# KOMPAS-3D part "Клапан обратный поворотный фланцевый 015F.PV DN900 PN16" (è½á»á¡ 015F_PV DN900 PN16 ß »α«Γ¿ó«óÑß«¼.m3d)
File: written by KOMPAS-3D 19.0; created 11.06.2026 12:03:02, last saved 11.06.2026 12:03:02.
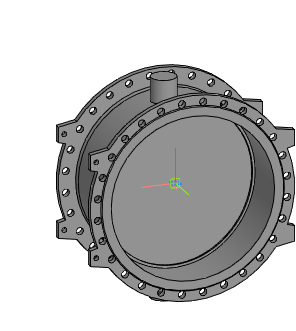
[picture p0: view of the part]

Document properties: Автор: Энергия; Полное имя файла: Z:\3.Личные\kachalov\001_3d для проектировщиков\5.5 Тип 015F.PV Клапан обратный поворотный с двумя эксцентриками\_stp_Клапан 015F.PV DN300-DN1200 с противовесом\Клапан 015F_PV DN900 PN16 с противовесом.m3d

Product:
- Part/product: Клапан обратный поворотный фланцевый 015F.PV DN900 PN16

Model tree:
1. Операция без истории:1
2. Сплайн:1
     Координата Y = 30; Координата Z = 450; Вес = 1; Координата X = 900; Координата Y = 148.487; Координата Z = 450; Вес = 0.333333; Координата X = 900; Координата Y = 148.487; Координата Z = -450; Вес = 0.333333; Координата Y = 30; Координата Z = -450; Вес = 1; Координата X = -900; Координата Y = -88.4872; Координата Z = -450; Вес = 0.333333; Координата X = -900; Координата Y = -88.4872; Координата Z = 450; Вес = 0.333333; Порядок = 4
